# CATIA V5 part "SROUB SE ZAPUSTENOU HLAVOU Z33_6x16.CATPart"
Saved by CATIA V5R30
Part number: SROUB SE ZAPUSTENOU HLAVOU Z33/6x16
Bounding box of the stored display mesh (mm): x 0 to 16, y -6 to 6, z -6 to 6
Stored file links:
  C:\Users\ondra\Desktop\PŘÍLOHA P III\CATIA\SROUB SE ZAPUSTENOU HLAVOU Z33_6x16.CATPart
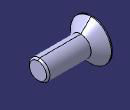
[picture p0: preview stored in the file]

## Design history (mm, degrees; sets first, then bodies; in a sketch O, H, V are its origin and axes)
Set1
  DatumSurface1 to DatumSurface24 "Z33/6x16"
  Join1: Elements (DatumSurface1; DatumSurface2; DatumSurface3; DatumSurface4; DatumSurface5; DatumSurface6; DatumSurface7; DatumSurface8; DatumSurface9; DatumSurface10; DatumSurface11; DatumSurface12; DatumSurface13; DatumSurface14; DatumSurface15; DatumSurface16; DatumSurface17; DatumSurface18; DatumSurface19; DatumSurface20; DatumSurface21; DatumSurface22; DatumSurface23; DatumSurface24)
Body1 (main body)
  CloseSurface1: CloseElement Join1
